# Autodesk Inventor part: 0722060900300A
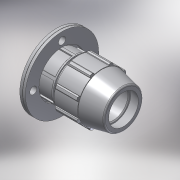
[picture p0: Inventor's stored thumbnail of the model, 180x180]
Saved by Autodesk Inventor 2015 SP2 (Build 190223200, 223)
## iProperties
Created: 2017-02
Part Number: 0722060900300A
Material: PVC-Piping
Description: PLASSON COMPRESSION FLANGE ADAPTOR 90-3"
Document SubType Name: Modeling
Designer: KIM
Mass: 92.6774 g
Surface Area: 199.44 cm^2
Volume: 66.1981 cm^3
Density: 1.4 g/cm^3
Appearance: Smooth - White
Author: KIM
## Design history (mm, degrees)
derived "87220.ipt"
feature "Solid1::87220.ipt"
tag "TaggingFeature1"
body "Solid1"
other parameters: "d4" = 27.85714, "d5" = 62.4, "d7" = 154, "d9" = 27.85714, "d11" = 5.57143, "d12" = 123.2, "d13" = 120 deg, "d14" = 117, "d15" = 12 deg, "d18" = 4.5, "d19" = 35 deg, "d20" = 17.5 deg, "d21" = 143.22, "d23" = 0, "d25" = 360 deg, "d27" = 3.08, "d34" = 7.7, "d36" = 0, "d42" = 68.25, "d43" = 4.62, "d46" = 2.7, "d53" = 1.8, "d55" = 360 deg, "d70" = 195, "d73" = 16.25, "d74" = 90 deg, "d75" = 0.3, "d77" = 18, "d80" = 0, "d82" = 360 deg, "d85" = 130.9, "d86" = 123.2, "d87" = 2.5, "d88" = 0.3, "d93" = 9.75, "d94" = 183, "E_" = 154, "H_" = 195, "l_" = 183, "S_" = 18
